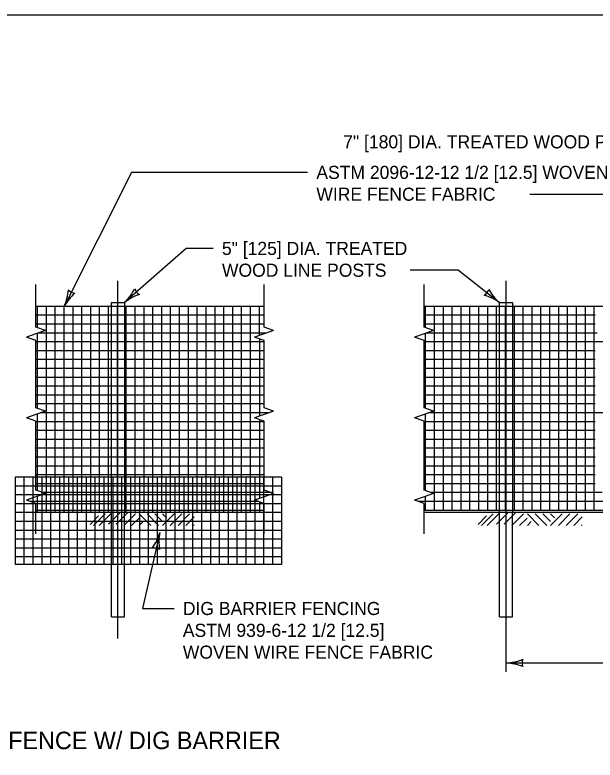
# Model space of a CAD drawing. Extents: x 49991.4 to 50021, y 49987.6 to 50011.4.
# Drawn here: x 50003.24 to 50005.896, y 49995.584 to 49998.999 of the extents above; entities that cross this region are included whole.
import ezdxf

# ---------------------------------------------------------------- set-up
doc = ezdxf.new("R2010")
doc.units = 0
for name, color, linetype in [('Level 1', 7, 'Continuous'), ('Level 2', 7, 'Continuous'), ('Level 3', 7, 'Continuous'), ('Level 4', 7, 'Continuous'), ('Level 5', 7, 'Continuous'), ('Level 6', 7, 'Continuous')]:
    doc.layers.add(name, color=color, linetype=linetype)

msp = doc.modelspace()

# ---------------------------------------------------------------- linework, layer by layer
at = {"layer": 'Level 1'}
for p, q in [((50004.3806, 49997.6633), (50003.336, 49997.6633)), ((50003.3431, 49997.5661), (50003.3431, 49997.6633)), ((50003.3838, 49996.7205), (50003.3838, 49997.6633)), ((50003.4244, 49996.7205), (50003.4244, 49997.6633)), ((50003.4651, 49996.7205), (50003.4651, 49997.6633)), ((50003.5057, 49996.7205), (50003.5057, 49997.6633)), ((50003.5463, 49996.7205), (50003.5463, 49997.6633)), ((50003.587, 49996.7205), (50003.587, 49997.6633)), ((50003.6276, 49996.7205), (50003.6276, 49997.6633)), ((50003.6683, 49996.7205), (50003.6683, 49997.6633)), ((50003.6818, 49996.7205), (50003.6818, 49997.6806)), ((50003.6818, 49997.6806), (50003.7418, 49997.6806)), ((50003.7089, 49996.7205), (50003.7089, 49997.6633)), ((50003.7418, 49997.6806), (50003.7418, 49996.7205)), ((50003.7496, 49996.7205), (50003.7496, 49997.6633)), ((50003.7902, 49996.7205), (50003.7902, 49997.6633)), ((50003.8308, 49996.7205), (50003.8308, 49997.6633)), ((50003.8715, 49996.7205), (50003.8715, 49997.6633)), ((50003.9121, 49996.7205), (50003.9121, 49997.6633)), ((50003.9528, 49996.7205), (50003.9528, 49997.6633)), ((50003.9934, 49996.7205), (50003.9934, 49997.6633)), ((50004.034, 49996.7205), (50004.034, 49997.6633)), ((50004.0747, 49996.7205), (50004.0747, 49997.6633)), ((50004.1153, 49996.7205), (50004.1153, 49997.6633)), ((50004.156, 49996.7205), (50004.156, 49997.6633)), ((50004.1966, 49996.7205), (50004.1966, 49997.6633)), ((50004.2373, 49996.7205), (50004.2373, 49997.6633)), ((50004.2779, 49996.7205), (50004.2779, 49997.6633)), ((50004.3185, 49996.7205), (50004.3185, 49997.6633)), ((50004.359, 49997.5303), (50004.359, 49997.6633)), ((50009.1438, 49997.6633), (50005.1131, 49997.6633)), ((50005.1202, 49997.5661), (50005.1202, 49997.6633)), ((50005.1609, 49996.7285), (50005.1609, 49997.6633)), ((50005.2015, 49996.7285), (50005.2015, 49997.6633)), ((50005.2422, 49996.7285), (50005.2422, 49997.6633)), ((50005.2828, 49996.7285), (50005.2828, 49997.6633)), ((50005.3235, 49996.7285), (50005.3235, 49997.6633)), ((50005.3641, 49996.7285), (50005.3641, 49997.6633)), ((50005.4048, 49996.7285), (50005.4048, 49997.6633)), ((50005.4454, 49996.7285), (50005.4454, 49997.6633)), ((50005.4589, 49996.7205), (50005.4589, 49997.6806)), ((50005.4589, 49997.6806), (50005.5189, 49997.6806)), ((50005.486, 49996.7285), (50005.486, 49997.6633)), ((50005.5189, 49997.6806), (50005.5189, 49996.7205)), ((50005.5267, 49996.7285), (50005.5267, 49997.6633)), ((50005.5673, 49996.7285), (50005.5673, 49997.6633)), ((50005.608, 49996.7285), (50005.608, 49997.6633)), ((50005.6486, 49996.7285), (50005.6486, 49997.6633)), ((50005.6893, 49996.7285), (50005.6893, 49997.6633)), ((50005.7299, 49996.7285), (50005.7299, 49997.6633)), ((50005.7705, 49996.7285), (50005.7705, 49997.6633)), ((50005.8112, 49996.7285), (50005.8112, 49997.6633)), ((50005.8518, 49996.7285), (50005.8518, 49997.6633)), ((50005.8925, 49996.7285), (50005.8925, 49997.6633)), ((50004.3806, 49997.6226), (50003.336, 49997.6226)), ((50005.8964, 49997.6226), (50005.1131, 49997.6226)), ((50004.3806, 49997.582), (50003.336, 49997.582)), ((50005.8964, 49997.582), (50005.1131, 49997.582)), ((50003.3431, 49997.1964), (50003.3431, 49997.5405)), ((50004.3899, 49997.5413), (50003.3454, 49997.5413)), ((50005.1202, 49997.1964), (50005.1202, 49997.5405)), ((50005.9058, 49997.5413), (50005.1225, 49997.5413)), ((50004.3806, 49997.5007), (50003.336, 49997.5007)), ((50004.359, 49997.515), (50004.359, 49997.1606)), ((50007.3299, 49997.5007), (50005.1131, 49997.5007)), ((50004.3806, 49997.4601), (50003.336, 49997.4601)), ((50005.8964, 49997.4601), (50005.1131, 49997.4601)), ((50004.3806, 49997.4194), (50003.336, 49997.4194)), ((50005.8964, 49997.4194), (50005.1131, 49997.4194)), ((50004.3806, 49997.3788), (50003.336, 49997.3788)), ((50005.8964, 49997.3788), (50005.1131, 49997.3788)), ((50004.3806, 49997.3381), (50003.336, 49997.3381)), ((50005.8964, 49997.3381), (50005.1131, 49997.3381)), ((50004.3806, 49997.2975), (50003.336, 49997.2975)), ((50005.8964, 49997.2975), (50005.1131, 49997.2975)), ((50004.3806, 49997.2568), (50003.336, 49997.2568)), ((50005.8964, 49997.2568), (50005.1131, 49997.2568)), ((50004.3806, 49997.2162), (50003.336, 49997.2162)), ((50005.8964, 49997.2162), (50005.1131, 49997.2162)), ((50004.4011, 49997.1756), (50003.3566, 49997.1756)), ((50006.8359, 49997.1756), (50005.1337, 49997.1756)), ((50003.3431, 49996.819), (50003.3431, 49997.1708)), ((50004.359, 49997.1453), (50004.359, 49996.7832)), ((50005.1202, 49996.819), (50005.1202, 49997.1708)), ((50004.3806, 49997.1349), (50003.336, 49997.1349)), ((50005.8964, 49997.1349), (50005.1131, 49997.1349)), ((50004.3806, 49997.0943), (50003.336, 49997.0943)), ((50005.8964, 49997.0943), (50005.1131, 49997.0943)), ((50004.3806, 49997.0536), (50003.336, 49997.0536)), ((50005.8964, 49997.0536), (50005.1131, 49997.0536)), ((50004.3806, 49997.013), (50003.336, 49997.013)), ((50005.8964, 49997.013), (50005.1131, 49997.013)), ((50004.3806, 49996.9724), (50003.336, 49996.9724)), ((50005.8964, 49996.9724), (50005.1131, 49996.9724)), ((50004.3806, 49996.9317), (50003.336, 49996.9317)), ((50005.8964, 49996.9317), (50005.1131, 49996.9317)), ((50003.2405, 49996.8805), (50003.2405, 49996.4805)), ((50004.4596, 49996.8805), (50003.2405, 49996.8805)), ((50003.2811, 49996.8805), (50003.2811, 49996.4805)), ((50003.3217, 49996.8805), (50003.3217, 49996.4805)), ((50004.3806, 49996.8911), (50003.336, 49996.8911)), ((50003.3624, 49996.8805), (50003.3624, 49996.4805)), ((50003.403, 49996.8805), (50003.403, 49996.4805)), ((50003.4437, 49996.8805), (50003.4437, 49996.4805)), ((50003.4843, 49996.8805), (50003.4843, 49996.4805)), ((50003.525, 49996.8805), (50003.525, 49996.4805)), ((50003.5656, 49996.8805), (50003.5656, 49996.4805)), ((50003.6062, 49996.8805), (50003.6062, 49996.4805)), ((50003.6469, 49996.8805), (50003.6469, 49996.4805)), ((50003.6875, 49996.8805), (50003.6875, 49996.4805)), ((50003.7282, 49996.8805), (50003.7282, 49996.4805)), ((50003.7688, 49996.8805), (50003.7688, 49996.4805)), ((50003.8095, 49996.8805), (50003.8095, 49996.4805)), ((50003.8501, 49996.8805), (50003.8501, 49996.4805)), ((50003.8907, 49996.8805), (50003.8907, 49996.4805)), ((50003.9314, 49996.8805), (50003.9314, 49996.4805)), ((50003.972, 49996.8805), (50003.972, 49996.4805)), ((50004.0127, 49996.8805), (50004.0127, 49996.4805)), ((50004.0533, 49996.8805), (50004.0533, 49996.4805)), ((50004.0939, 49996.8805), (50004.0939, 49996.4805)), ((50004.1346, 49996.8805), (50004.1346, 49996.4805)), ((50004.1752, 49996.8805), (50004.1752, 49996.4805)), ((50004.2159, 49996.8805), (50004.2159, 49996.4805)), ((50004.2565, 49996.8805), (50004.2565, 49996.4805)), ((50004.2972, 49996.8805), (50004.2972, 49996.4805)), ((50004.3378, 49996.8805), (50004.3378, 49996.4805)), ((50004.3784, 49996.8805), (50004.3784, 49996.4805)), ((50004.419, 49996.8805), (50004.419, 49996.4805)), ((50004.4596, 49996.8805), (50004.4596, 49996.4805)), ((50005.8964, 49996.8911), (50005.1131, 49996.8911)), ((50004.4596, 49996.8399), (50003.2405, 49996.8399)), ((50004.3806, 49996.8504), (50003.336, 49996.8504)), ((50005.8964, 49996.8504), (50005.1131, 49996.8504)), ((50004.4596, 49996.7992), (50003.2405, 49996.7992)), ((50004.4139, 49996.8098), (50003.3692, 49996.8098)), ((50005.9294, 49996.8098), (50005.1463, 49996.8098)), ((50004.0938, 49996.7691), (50003.3106, 49996.7691)), ((50003.3431, 49996.7205), (50003.3431, 49996.7934)), ((50004.3552, 49996.7692), (50004.0938, 49996.7692)), ((50004.359, 49996.7679), (50004.359, 49996.7205)), ((50005.8709, 49996.7691), (50005.0878, 49996.7691)), ((50005.1202, 49996.7285), (50005.1202, 49996.7934)), ((50009.1438, 49996.7692), (50005.8709, 49996.7692)), ((50004.4596, 49996.7586), (50003.2405, 49996.7586)), ((50004.4596, 49996.718), (50003.2405, 49996.718)), ((50004.3806, 49996.7285), (50003.336, 49996.7285)), ((50003.336, 49996.7205), (50004.3806, 49996.7205)), ((50003.5837, 49996.6638), (50003.6216, 49996.7029)), ((50003.5995, 49996.6589), (50003.6528, 49996.7121)), ((50003.6253, 49996.6597), (50003.6786, 49996.713)), ((50003.6675, 49996.6647), (50003.7208, 49996.7179)), ((50003.703, 49996.6647), (50003.7562, 49996.7179)), ((50003.738, 49996.6591), (50003.7913, 49996.7124)), ((50003.738, 49996.6591), (50003.7913, 49996.7124)), ((50003.8623, 49996.6591), (50003.809, 49996.7124)), ((50003.8978, 49996.6591), (50003.8446, 49996.7124)), ((50003.9156, 49996.6769), (50003.88, 49996.7124)), ((50003.9156, 49996.6591), (50003.9688, 49996.7124)), ((50003.9156, 49996.6591), (50003.9688, 49996.7124)), ((50003.9333, 49996.6946), (50003.9156, 49996.7124)), ((50003.951, 49996.6591), (50004.0043, 49996.7124)), ((50003.951, 49996.6591), (50004.0043, 49996.7124)), ((50003.9866, 49996.6591), (50004.0398, 49996.7124)), ((50003.9866, 49996.6591), (50004.0398, 49996.7124)), ((50004.0221, 49996.6591), (50004.0599, 49996.6982)), ((50004.0221, 49996.6591), (50004.0599, 49996.6982)), ((50009.1438, 49996.7285), (50005.1131, 49996.7285)), ((50005.1131, 49996.7205), (50009.738, 49996.7205)), ((50005.3609, 49996.6638), (50005.3987, 49996.7029)), ((50005.3767, 49996.6589), (50005.4299, 49996.7121)), ((50005.4024, 49996.6597), (50005.4557, 49996.713)), ((50005.4446, 49996.6647), (50005.4979, 49996.7179)), ((50005.4801, 49996.6647), (50005.5334, 49996.7179)), ((50005.5152, 49996.6591), (50005.5684, 49996.7124)), ((50005.5152, 49996.6591), (50005.5684, 49996.7124)), ((50005.6394, 49996.6591), (50005.5862, 49996.7124)), ((50005.6749, 49996.6591), (50005.6217, 49996.7124)), ((50005.6927, 49996.6769), (50005.6572, 49996.7124)), ((50005.6927, 49996.6591), (50005.7459, 49996.7124)), ((50005.6927, 49996.6591), (50005.7459, 49996.7124)), ((50005.7105, 49996.6946), (50005.6927, 49996.7124)), ((50005.7282, 49996.6591), (50005.7815, 49996.7124)), ((50005.7282, 49996.6591), (50005.7815, 49996.7124)), ((50005.7637, 49996.6591), (50005.8169, 49996.7124)), ((50005.7637, 49996.6591), (50005.8169, 49996.7124)), ((50005.7992, 49996.6591), (50005.8371, 49996.6982)), ((50005.7992, 49996.6591), (50005.8371, 49996.6982)), ((50004.4596, 49996.6773), (50003.2405, 49996.6773)), ((50003.7735, 49996.6591), (50003.8078, 49996.6934)), ((50003.809, 49996.6591), (50003.8268, 49996.6769)), ((50004.0576, 49996.6591), (50004.0599, 49996.6627)), ((50005.5506, 49996.6591), (50005.585, 49996.6934)), ((50005.5862, 49996.6591), (50005.6039, 49996.6769)), ((50005.8347, 49996.6591), (50005.8371, 49996.6627)), ((50004.4596, 49996.6367), (50003.2405, 49996.6367)), ((50004.4596, 49996.596), (50003.2405, 49996.596)), ((50004.4596, 49996.5554), (50003.2405, 49996.5554)), ((50004.4596, 49996.5148), (50003.2405, 49996.5148)), ((50004.4596, 49996.4805), (50003.2405, 49996.4805))]:
    msp.add_line(p, q, dxfattribs=at)
msp.add_lwpolyline([(49999.3835, 49998.9992), (50016.7501, 49998.9992), (50016.7501, 49987.7988), (49999.3835, 49987.7988)], close=True, dxfattribs=at)
at = {"layer": 'Level 2'}
msp.add_line((50005.8925, 49997.6615), (50005.8953, 49997.6676), dxfattribs=at)
at = {"layer": 'Level 3'}
for p, q in [((50003.7738, 49998.2775), (50003.4651, 49997.6633)), ((50004.58, 49998.2775), (50003.7738, 49998.2775)), ((50005.5973, 49998.1775), (50006.1655, 49998.1775)), ((50004.0244, 49997.9291), (50003.7417, 49997.6806)), ((50004.1476, 49997.9291), (50004.0244, 49997.9291)), ((50005.271, 49997.8291), (50005.4589, 49997.6806)), ((50003.9026, 49996.627), (50003.8231, 49996.2787)), ((50003.8231, 49996.2787), (50003.9685, 49996.2787)), ((50005.4888, 49996.029), (50007.3291, 49996.029))]:
    msp.add_line(p, q, dxfattribs=at)
msp.add_lwpolyline([(50005.271, 49997.8291), (50005.0497, 49997.8291)], dxfattribs=at)
for centre, radius, start, end in [((50003.252, 49997.7575), 0.233, 336.1423, 355.3921), ((50003.6594, 49997.5553), 0.2223, 130.771, 150.9545), ((50003.5226, 49997.7778), 0.0548, 225.4538, 261.1762), ((50003.5795, 49997.8477), 0.233, 314.1502, 333.4), ((50003.838, 49997.7652), 0.0548, 203.4617, 239.184), ((50005.3583, 49997.7601), 0.0548, 303.809, 339.5313), ((50005.6039, 49997.8491), 0.2223, 209.1262, 229.3097), ((50003.8815, 49997.5077), 0.2223, 108.7789, 128.9624), ((50005.3236, 49997.4909), 0.233, 54.4975, 73.7473), ((50003.688, 49996.6854), 0.2223, 324.6029, 344.7864), ((50004.132, 49996.5864), 0.233, 169.9742, 189.2241), ((50003.8741, 49996.502), 0.0548, 59.2857, 95.0081), ((50005.4773, 49996.2617), 0.233, 272.8273, 292.0772), ((50005.4796, 49995.8068), 0.2223, 67.456, 87.6395), ((50005.617, 49996.029), 0.0548, 162.1388, 197.8612)]:
    msp.add_arc(centre, radius, start, end, dxfattribs=at)
at = {"layer": 'Level 4'}
for p, q in [((50003.6818, 49996.2405), (50003.6818, 49996.7205)), ((50003.7418, 49996.2405), (50003.7418, 49996.7205)), ((50005.4589, 49996.2405), (50005.4589, 49996.7205)), ((50005.5189, 49996.2405), (50005.5189, 49996.7205)), ((50003.6818, 49996.2405), (50003.7418, 49996.2405)), ((50005.4589, 49996.2405), (50005.5189, 49996.2405))]:
    msp.add_line(p, q, dxfattribs=at)
at = {"layer": 'Level 5'}
for p, q in [((50003.7116, 49996.1405), (50003.7116, 49997.7806)), ((50005.4888, 49995.989), (50005.4888, 49997.7806))]:
    msp.add_line(p, q, dxfattribs=at)
at = {"layer": 'Level 6'}
for p, q in [((50003.336, 49997.5687), (50003.336, 49997.7633)), ((50004.3806, 49997.5687), (50004.3806, 49997.7633)), ((50005.1131, 49997.5687), (50005.1131, 49997.7633)), ((50003.3793, 49997.5534), (50003.336, 49997.5687)), ((50003.3793, 49997.5534), (50003.336, 49997.538)), ((50004.4239, 49997.5534), (50004.3806, 49997.5687)), ((50004.4239, 49997.5534), (50004.3806, 49997.538)), ((50005.1564, 49997.5534), (50005.1131, 49997.5687)), ((50005.1564, 49997.5534), (50005.1131, 49997.538)), ((50003.336, 49997.538), (50003.2927, 49997.5226)), ((50003.336, 49997.5074), (50003.2927, 49997.5226)), ((50004.3806, 49997.538), (50004.3373, 49997.5226)), ((50004.3806, 49997.5074), (50004.3373, 49997.5226)), ((50005.1131, 49997.538), (50005.0698, 49997.5226)), ((50005.1131, 49997.5074), (50005.0698, 49997.5226)), ((50003.336, 49997.1989), (50003.336, 49997.5073)), ((50004.3806, 49997.1989), (50004.3806, 49997.5074)), ((50005.1131, 49997.1989), (50005.1131, 49997.5073)), ((50003.3793, 49997.1836), (50003.336, 49997.1989)), ((50003.3793, 49997.1836), (50003.336, 49997.1683)), ((50004.4239, 49997.1837), (50004.3806, 49997.1989)), ((50004.4239, 49997.1837), (50004.3806, 49997.1683)), ((50005.1564, 49997.1836), (50005.1131, 49997.1989)), ((50005.1564, 49997.1836), (50005.1131, 49997.1683)), ((50003.336, 49997.1683), (50003.2927, 49997.1529)), ((50003.336, 49997.1376), (50003.2927, 49997.1529)), ((50004.3806, 49997.1683), (50004.3373, 49997.1529)), ((50004.3806, 49997.1377), (50004.3373, 49997.1529)), ((50005.1131, 49997.1683), (50005.0698, 49997.1529)), ((50005.1131, 49997.1376), (50005.0698, 49997.1529)), ((50003.336, 49996.8215), (50003.336, 49997.1376)), ((50004.3806, 49996.8215), (50004.3806, 49997.1377)), ((50005.1131, 49996.8215), (50005.1131, 49997.1376)), ((50003.3793, 49996.8062), (50003.336, 49996.8215)), ((50003.3793, 49996.8062), (50003.336, 49996.7909)), ((50004.4239, 49996.8062), (50004.3806, 49996.8215)), ((50004.4239, 49996.8062), (50004.3806, 49996.7909)), ((50005.1564, 49996.8062), (50005.1131, 49996.8215)), ((50005.1564, 49996.8062), (50005.1131, 49996.7909)), ((50003.336, 49996.7909), (50003.2927, 49996.7755)), ((50003.336, 49996.7602), (50003.2927, 49996.7755)), ((50004.3806, 49996.7909), (50004.3373, 49996.7755)), ((50004.3806, 49996.7602), (50004.3373, 49996.7755)), ((50005.1131, 49996.7909), (50005.0698, 49996.7755)), ((50005.1131, 49996.7602), (50005.0698, 49996.7755)), ((50003.336, 49996.6205), (50003.336, 49996.7602)), ((50004.3806, 49996.6205), (50004.3806, 49996.7602)), ((50005.1131, 49996.6205), (50005.1131, 49996.7602))]:
    msp.add_line(p, q, dxfattribs=at)

# ---------------------------------------------------------------- texts
at = {"layer": 'Level 2'}
for s, height, p in [('7" [180] DIA. TREATED WOOD POSTS', 0.060003, (50004.743, 49998.3875)), ('ASTM 2096-12-12 1/2 [12.5] WOVEN', 0.06, (50004.62, 49998.2475)), ('WIRE FENCE FABRIC', 0.06, (50004.62, 49998.1475)), ('5" [125] DIA. TREATED', 0.06, (50004.1876, 49997.8991)), ('WOOD LINE POSTS', 0.06, (50004.1876, 49997.7991)), ('DIG BARRIER FENCING', 0.06, (50004.0085, 49996.2487)), ('ASTM 939-6-12 1/2 [12.5] ', 0.06, (50004.0085, 49996.1487)), ('WOVEN WIRE FENCE FABRIC', 0.06, (50004.0085, 49996.0487)), ('WILDLIFE FENCE W/ DIG BARRIER', 0.08, (50002.6856, 49995.634))]:
    msp.add_text(s, height=height, dxfattribs=at).set_placement(p)

doc.saveas('drawing.dxf')
